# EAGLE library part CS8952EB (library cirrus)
ETHERNET TRANSCEIVER CrystalLAN 100BASE-X and 10BASE-T Transceiver
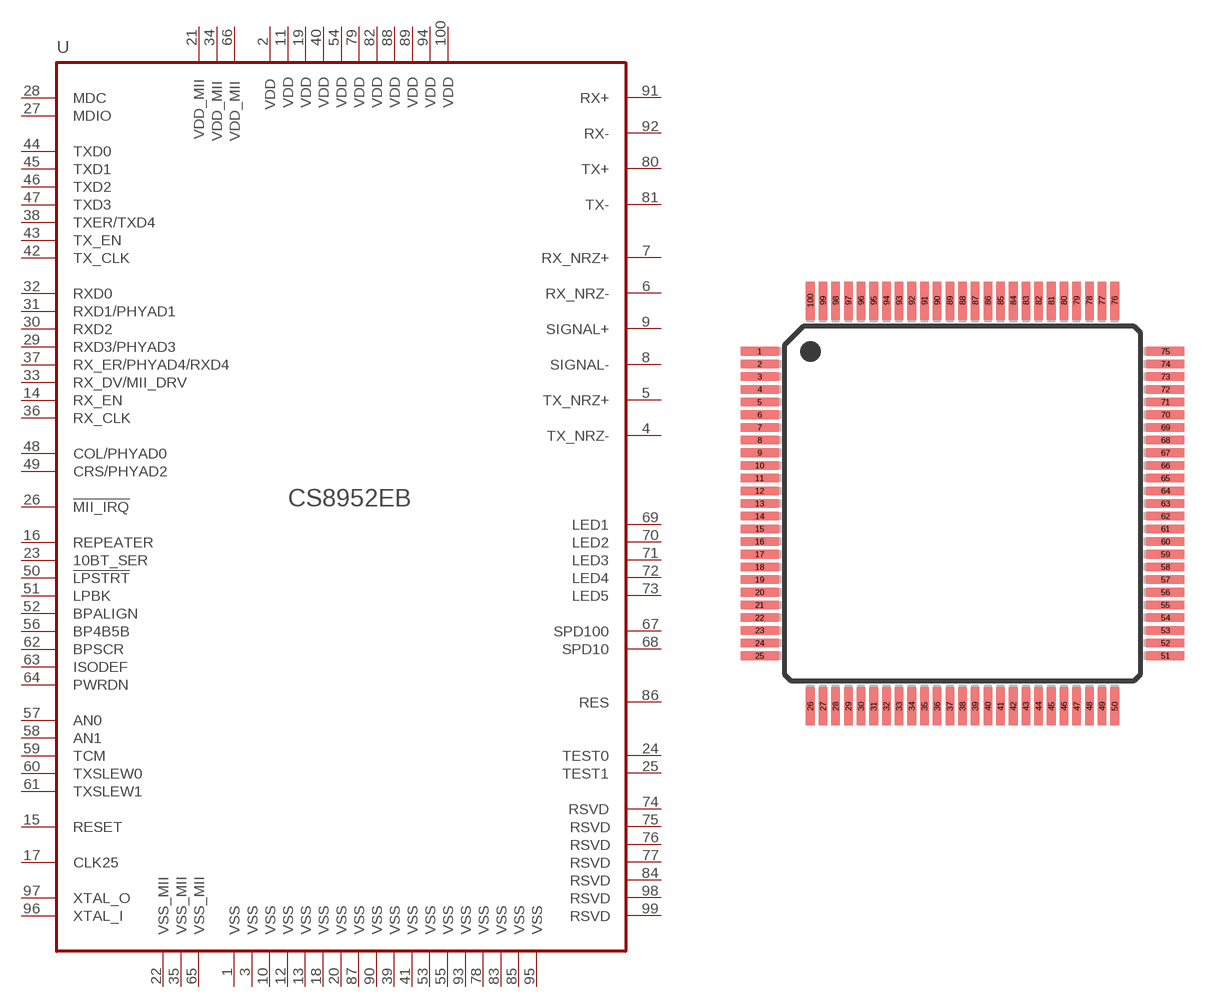
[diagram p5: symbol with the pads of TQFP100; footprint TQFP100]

Designator prefix U

## CS8952EB  [TQFP100]
1  VSS  pwr
2  VDD  pwr
3  VSS1  pwr
4  TX_NRZ-
5  TX_NRZ+
6  RX_NRZ-
7  RX_NRZ+
8  SIGNAL-
9  SIGNAL+
10  VSS2  pwr
11  VDD1  pwr
12  VSS3  pwr
13  VSS4  pwr
14  RX_EN
15  RESET  in
16  REPEATER
17  CLK25  out
18  VSS5  pwr
19  VDD2  pwr
20  VSS6  pwr
21  VDD_MII  pwr
22  VSS_MII  pwr
23  10BT_SER
24  TEST0
25  TEST1  in
26  MII_IRQ  out
27  MDIO
28  MDC  in
29  RXD3/PHYAD3  out
30  RXD2  out
31  RXD1/PHYAD1  out
32  RXD0  out
33  RX_DV/MII_DRV
34  VDD_MII1  pwr
35  VSS_MII1  pwr
36  RX_CLK  out
37  RX_ER/PHYAD4/RXD4
38  TXER/TXD4
39  VSS9  pwr
40  VDD3  pwr
41  VSS10  pwr
42  TX_CLK
43  TX_EN  in
44  TXD0  in
45  TXD1  in
46  TXD2  in
47  TXD3  in
48  COL/PHYAD0  out
49  CRS/PHYAD2
50  LPSTRT  in
51  LPBK  in
52  BPALIGN
53  VSS11  pwr
54  VDD4  pwr
55  VSS12  pwr
56  BP4B5B
57  AN0
58  AN1
59  TCM  in
60  TXSLEW0  in
61  TXSLEW1  in
62  BPSCR
63  ISODEF
64  PWRDN  in
65  VSS_MII2  pwr
66  VDD_MII2  pwr
67  SPD100  out
68  SPD10  out
69  LED1  out
70  LED2  out
71  LED3  out
72  LED4  out
73  LED5  out
74  RSVD  pwr
75  RSVD1  pwr
76  RSVD2  pwr
77  RSVD3  pwr
78  VSS14  pwr
79  VDD5  pwr
80  TX+  out
81  TX-  out
82  VDD6  pwr
83  VSS15  pwr
84  RSVD4  pwr
85  VSS16  pwr
86  RES
87  VSS7  pwr
88  VDD7  pwr
89  VDD8  pwr
90  VSS8  pwr
91  RX+  in
92  RX-  in
93  VSS13  pwr
94  VDD9  pwr
95  VSS17  pwr
96  XTAL_I  pas
97  XTAL_O  pas
98  RSVD5  pwr
99  RSVD6  pwr
100  VDD10  pwr

## Footprint TQFP100 (pad centres in mm)
Plastic Thin Quad Flat Pack
smd 1.5 x 0.34: 1 -8,6; 2 -8,5.5; 3 -8,5; 4 -8,4.5; 5 -8,4; 6 -8,3.5; 7 -8,3; 8 -8,2.5; 9 -8,2; 10 -8,1.5; 11 -8,1; 12 -8,0.5; 13 -8,0; 14 -8,-0.5; 15 -8,-1; 16 -8,-1.5; 17 -8,-2; 18 -8,-2.5; 19 -8,-3; 20 -8,-3.5; 21 -8,-4; 22 -8,-4.5; 23 -8,-5; 24 -8,-5.5; 25 -8,-6; 51 8,-6; 52 8,-5.5; 53 8,-5; 54 8,-4.5; 55 8,-4; 56 8,-3.5; 57 8,-3; 58 8,-2.5; 59 8,-2; 60 8,-1.5; 61 8,-1; 62 8,-0.5; 63 8,0; 64 8,0.5; 65 8,1; 66 8,1.5; 67 8,2; 68 8,2.5; 69 8,3; 70 8,3.5; 71 8,4; 72 8,4.5; 73 8,5; 74 8,5.5; 75 8,6
smd 0.34 x 1.5: 26 -6,-8; 27 -5.5,-8; 28 -5,-8; 29 -4.5,-8; 30 -4,-8; 31 -3.5,-8; 32 -3,-8; 33 -2.5,-8; 34 -2,-8; 35 -1.5,-8; 36 -1,-8; 37 -0.5,-8; 38 0,-8; 39 0.5,-8; 40 1,-8; 41 1.5,-8; 42 2,-8; 43 2.5,-8; 44 3,-8; 45 3.5,-8; 46 4,-8; 47 4.5,-8; 48 5,-8; 49 5.5,-8; 50 6,-8; 76 6,8; 77 5.5,8; 78 5,8; 79 4.5,8; 80 4,8; 81 3.5,8; 82 3,8; 83 2.5,8; 84 2,8; 85 1.5,8; 86 1,8; 87 0.5,8; 88 0,8; 89 -0.5,8; 90 -1,8; 91 -1.5,8; 92 -2,8; 93 -2.5,8; 94 -3,8; 95 -3.5,8; 96 -4,8; 97 -4.5,8; 98 -5,8; 99 -5.5,8; 100 -6,8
